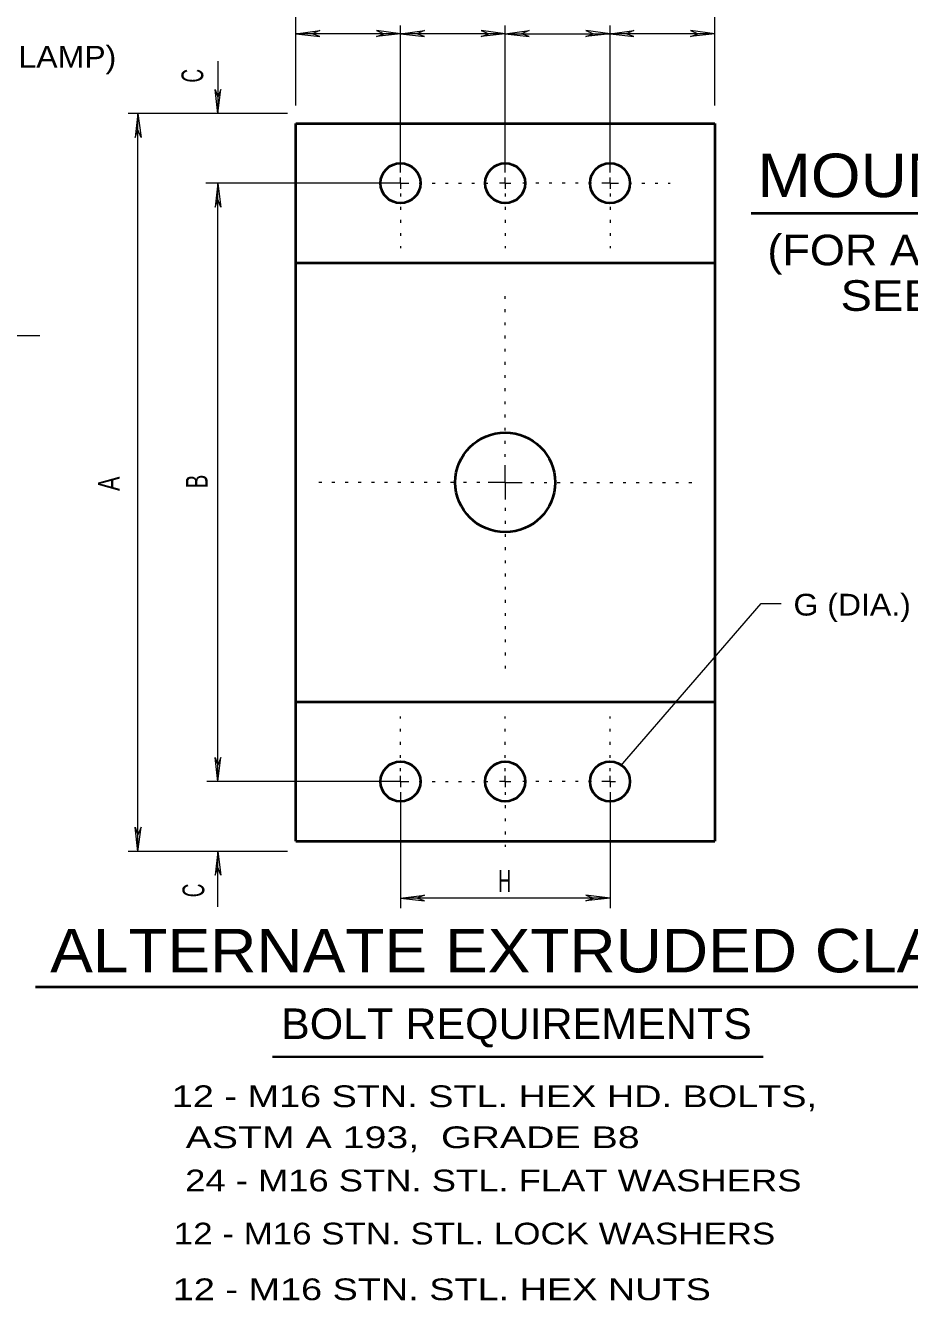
# Model space of a CAD drawing. Extents: x 312583 to 312854, y 144419 to 144597.
# Drawn here: x 312654.71 to 312685.59, y 144472.22 to 144516.78 of the extents above; entities that cross this region are included whole.
import ezdxf
from ezdxf.enums import TextEntityAlignment as Align

# ---------------------------------------------------------------- set-up
doc = ezdxf.new("R2010")
doc.units = 0
doc.header["$LTSCALE"] = 0.3
doc.linetypes.add('DOTTED', pattern=[1.5, 0.3, -1.2])
doc.layers.add('1', color=7, linetype='Continuous', lineweight=13)

msp = doc.modelspace()

# ---------------------------------------------------------------- linework, layer by layer
at = {"layer": '1'}
for p, q in [((312664.151, 144513.9841), (312664.151, 144519.5578)), ((312678.7867, 144513.9841), (312678.7867, 144519.5578)), ((312664.151, 144516.4911), (312664.9867, 144516.5985)), ((312667.9843, 144516.4911), (312664.151, 144516.4911)), ((312664.151, 144516.4911), (312664.9867, 144516.3915)), ((312664.9867, 144516.5985), (312664.7183, 144516.4911)), ((312664.9867, 144516.3915), (312664.7183, 144516.4911)), ((312666.9723, 144516.5985), (312667.2407, 144516.4911)), ((312667.808, 144516.4911), (312666.9723, 144516.5985)), ((312666.9723, 144516.3915), (312667.2407, 144516.4911)), ((312667.808, 144516.4911), (312666.9723, 144516.3915)), ((312671.465, 144516.4911), (312667.6317, 144516.4911)), ((312667.808, 144511.6381), (312667.808, 144516.7748)), ((312667.808, 144516.4911), (312668.6513, 144516.5985)), ((312667.808, 144516.4911), (312668.6513, 144516.3915)), ((312668.6513, 144516.5985), (312668.383, 144516.4911)), ((312668.6513, 144516.3915), (312668.383, 144516.4911)), ((312670.6293, 144516.5985), (312670.8977, 144516.4911)), ((312671.465, 144516.4911), (312670.6293, 144516.5985)), ((312670.6293, 144516.3915), (312670.8977, 144516.4911)), ((312671.465, 144516.4911), (312670.6293, 144516.3915)), ((312671.465, 144511.6381), (312671.465, 144516.7748)), ((312671.465, 144516.4911), (312672.3083, 144516.5985)), ((312671.465, 144516.4911), (312672.3083, 144516.3915)), ((312671.4727, 144516.4911), (312675.306, 144516.4911)), ((312672.3083, 144516.5985), (312672.04, 144516.4911)), ((312672.3083, 144516.3915), (312672.04, 144516.4911)), ((312674.2863, 144516.5985), (312674.5547, 144516.4911)), ((312675.1297, 144516.4911), (312674.2863, 144516.5985)), ((312674.2863, 144516.3915), (312674.5547, 144516.4911)), ((312675.1297, 144516.4911), (312674.2863, 144516.3915)), ((312678.7867, 144516.4911), (312674.9533, 144516.4911)), ((312675.1297, 144511.6381), (312675.1297, 144516.7748)), ((312675.1297, 144516.4911), (312675.9653, 144516.5985)), ((312675.1297, 144516.4911), (312675.9653, 144516.3915)), ((312675.9653, 144516.5985), (312675.697, 144516.4911)), ((312675.9653, 144516.3915), (312675.697, 144516.4911)), ((312677.9433, 144516.5985), (312678.2117, 144516.4911)), ((312678.7867, 144516.4911), (312677.9433, 144516.5985)), ((312677.9433, 144516.3915), (312678.2117, 144516.4911)), ((312678.7867, 144516.4911), (312677.9433, 144516.3915)), ((312661.4293, 144515.5328), (312661.4293, 144513.7081)), ((312661.3297, 144514.5438), (312661.4293, 144514.2755)), ((312661.4293, 144513.7081), (312661.3297, 144514.5438)), ((312661.5367, 144514.5438), (312661.4293, 144514.2755)), ((312661.4293, 144513.7081), (312661.5367, 144514.5438)), ((312663.8673, 144513.7081), (312658.2937, 144513.7081)), ((312658.6387, 144513.7081), (312658.539, 144512.8648)), ((312658.6387, 144513.7081), (312658.746, 144512.8648)), ((312658.6387, 144487.9175), (312658.6387, 144513.7081)), ((312658.539, 144512.8648), (312658.6387, 144513.1331)), ((312658.746, 144512.8648), (312658.6387, 144513.1331)), ((312667.6163, 144511.2701), (312661.0077, 144511.2701)), ((312661.4293, 144511.2701), (312661.3297, 144510.4268)), ((312661.4293, 144511.2701), (312661.5367, 144510.4268)), ((312661.4293, 144490.3555), (312661.4293, 144511.2701)), ((312667.808, 144511.2701), (312667.6087, 144511.2701)), ((312667.808, 144511.2701), (312667.808, 144511.4618)), ((312667.808, 144511.2701), (312668.0073, 144511.2701)), ((312667.808, 144511.2701), (312667.808, 144511.0708)), ((312671.465, 144511.2701), (312671.2657, 144511.2701)), ((312671.465, 144511.2701), (312671.465, 144511.4618)), ((312671.465, 144511.2701), (312671.6643, 144511.2701)), ((312671.465, 144511.2701), (312671.465, 144511.0708)), ((312675.1297, 144511.2701), (312674.9303, 144511.2701)), ((312675.1297, 144511.2701), (312675.1297, 144511.4618)), ((312675.1297, 144511.2701), (312675.3213, 144511.2701)), ((312675.1297, 144511.2701), (312675.1297, 144511.0708)), ((312661.3297, 144510.4268), (312661.4293, 144510.6951)), ((312661.5367, 144510.4268), (312661.4293, 144510.6951)), ((312655.2106, 144505.934), (312652.5493, 144505.934)), ((312671.465, 144500.8128), (312671.465, 144501.4108)), ((312671.465, 144500.8128), (312670.867, 144500.8128)), ((312671.465, 144500.8128), (312672.063, 144500.8128)), ((312671.465, 144500.8128), (312671.465, 144500.2148)), ((312675.4977, 144490.8998), (312680.4043, 144496.5808)), ((312680.4043, 144496.5808), (312681.102, 144496.5808)), ((312661.3297, 144491.1988), (312661.4293, 144490.9305)), ((312661.4293, 144490.3555), (312661.3297, 144491.1988)), ((312661.5367, 144491.1988), (312661.4293, 144490.9305)), ((312661.4293, 144490.3555), (312661.5367, 144491.1988)), ((312667.808, 144490.3555), (312667.808, 144490.5548)), ((312671.465, 144490.3555), (312671.465, 144490.5548)), ((312675.1297, 144490.3555), (312675.1297, 144490.5548)), ((312667.6163, 144490.3555), (312661.046, 144490.3555)), ((312667.808, 144490.3555), (312667.6087, 144490.3555)), ((312667.808, 144490.3555), (312668.0073, 144490.3555)), ((312667.808, 144490.3555), (312667.808, 144490.1638)), ((312671.465, 144490.3555), (312671.2657, 144490.3555)), ((312671.465, 144490.3555), (312671.6643, 144490.3555)), ((312671.465, 144490.3555), (312671.465, 144490.1638)), ((312675.1297, 144490.3555), (312674.9303, 144490.3555)), ((312675.1297, 144490.3555), (312675.3213, 144490.3555)), ((312675.1297, 144490.3555), (312675.1297, 144490.1638)), ((312667.808, 144489.9875), (312667.808, 144485.9318)), ((312675.1297, 144489.9875), (312675.1297, 144485.9318)), ((312658.539, 144488.7608), (312658.6387, 144488.4925)), ((312658.6387, 144487.9175), (312658.539, 144488.7608)), ((312658.746, 144488.7608), (312658.6387, 144488.4925)), ((312658.6387, 144487.9175), (312658.746, 144488.7608)), ((312663.8673, 144487.9175), (312658.2937, 144487.9175)), ((312661.4293, 144487.9175), (312661.3297, 144487.0818)), ((312661.4293, 144485.9778), (312661.4293, 144487.9175)), ((312661.4293, 144487.9175), (312661.5367, 144487.0818)), ((312661.3297, 144487.0818), (312661.4293, 144487.3501)), ((312661.5367, 144487.0818), (312661.4293, 144487.3501)), ((312667.808, 144486.2845), (312668.6513, 144486.3918)), ((312667.808, 144486.2845), (312668.6513, 144486.1848)), ((312674.9533, 144486.2845), (312667.9843, 144486.2845)), ((312668.6513, 144486.3918), (312668.383, 144486.2845)), ((312668.6513, 144486.1848), (312668.383, 144486.2845)), ((312674.2863, 144486.3918), (312674.5547, 144486.2845)), ((312675.1297, 144486.2845), (312674.2863, 144486.3918)), ((312674.2863, 144486.1848), (312674.5547, 144486.2845)), ((312675.1297, 144486.2845), (312674.2863, 144486.1848))]:
    msp.add_line(p, q, dxfattribs=at)
at = {"layer": '1', "lineweight": 40}
for p, q in [((312664.151, 144513.3555), (312678.7867, 144513.3555)), ((312664.151, 144488.2701), (312664.151, 144513.3555)), ((312678.7867, 144513.3555), (312678.7867, 144488.2701)), ((312680.0639, 144510.2226), (312709.0439, 144510.2226)), ((312664.151, 144508.4795), (312678.7867, 144508.4795)), ((312664.151, 144493.1461), (312678.7867, 144493.1461)), ((312664.151, 144488.2701), (312678.7867, 144488.2701)), ((312655.0601, 144483.1871), (312689.9282, 144483.1871))]:
    msp.add_line(p, q, dxfattribs=at)
at = {"layer": '1', "linetype": 'DOTTED'}
for p, q in [((312667.6163, 144511.2701), (312666.083, 144511.2701)), ((312667.9997, 144511.2701), (312671.051, 144511.2701)), ((312674.938, 144511.2701), (312671.8867, 144511.2701)), ((312675.3213, 144511.2701), (312677.2303, 144511.2701)), ((312667.808, 144510.9021), (312667.808, 144508.9931)), ((312671.465, 144510.9021), (312671.465, 144508.9931)), ((312675.1297, 144510.9021), (312675.1297, 144508.9931)), ((312671.465, 144501.7021), (312671.465, 144507.6515)), ((312670.5757, 144500.8128), (312664.6263, 144500.8128)), ((312672.362, 144500.8128), (312678.3037, 144500.8128)), ((312671.465, 144499.9235), (312671.465, 144493.9741)), ((312667.808, 144490.7235), (312667.808, 144492.6325)), ((312671.465, 144490.7235), (312671.465, 144492.6325)), ((312675.1297, 144490.7235), (312675.1297, 144492.6325)), ((312667.9997, 144490.3555), (312671.051, 144490.3555)), ((312674.938, 144490.3555), (312671.8867, 144490.3555)), ((312671.465, 144489.9875), (312671.465, 144488.0785))]:
    msp.add_line(p, q, dxfattribs=at)
at = {"layer": '1', "lineweight": 35}
msp.add_line((312663.3383, 144480.7338), (312680.481, 144480.7338), dxfattribs=at)
at = {"layer": '1', "lineweight": 40}
for centre, radius in [((312667.8087, 144511.2673), 0.697), ((312671.4664, 144511.2673), 0.697), ((312675.1269, 144511.2673), 0.697), ((312671.4664, 144500.8128), 1.7424), ((312667.8087, 144490.3583), 0.697), ((312671.4664, 144490.3583), 0.697), ((312675.1269, 144490.3583), 0.697)]:
    msp.add_circle(centre, radius, dxfattribs=at)

# ---------------------------------------------------------------- texts
at = {"layer": '1'}
for s, height, width, p in [('SEE BOLT REQUIREMENTS (EXTRUDED CLAMP)', 0.76, 1.1, (312631.7306, 144515.304)), ('MOUNTING STRAP DETAIL', 1.52, 1.1, (312680.2791, 144510.7806)), ('G (DIA.)', 0.76, 1.1, (312681.5362, 144496.1582)), ('H', 0.76, 0.6, (312671.2283, 144486.501)), ('ALTERNATE EXTRUDED CLAMP', 1.52, 1.1, (312655.5716, 144483.6895)), (' 12 - M16 STN. STL. HEX HD. BOLTS,', 0.76, 1.3, (312659.4531, 144478.9799)), ('        ASTM A 193,  GRADE B8', 0.76, 1.35, (312657.2528, 144477.5462)), ('24 - M16 STN. STL. FLAT WASHERS', 0.76, 1.25, (312660.2867, 144476.0359)), (' 12 - M16 STN. STL. LOCK WASHERS', 0.76, 1.2, (312659.551, 144474.1806)), (' 12 - M16 STN. STL. HEX NUTS', 0.76, 1.3, (312659.4897, 144472.2332))]:
    msp.add_text(s, height=height, dxfattribs=dict(at, width=width)).set_placement(p)
for s, width, p in [('C', 0.65, (312660.9183, 144514.7829)), ('A', 0.75, (312658.005, 144500.5102)), ('B', 0.7, (312661.0715, 144500.6063)), ('C', 0.65, (312660.9537, 144486.3137))]:
    msp.add_text(s, height=0.76, rotation=90, dxfattribs=dict(at, width=width)).set_placement(p)
for s, width, p in [('(FOR ALTERNATE MOUNTING STRAP', 1.1, (312694.7456, 144508.3979)), ('SEE DETAIL ON THIS SHEET)', 1.15, (312694.7455, 144506.8066)), ('BOLT REQUIREMENTS', 1.05, (312671.8595, 144481.3584))]:
    msp.add_text(s, height=1.07, dxfattribs=dict(at, width=width)).set_placement(p, align=Align.CENTER)

doc.saveas('drawing.dxf')
